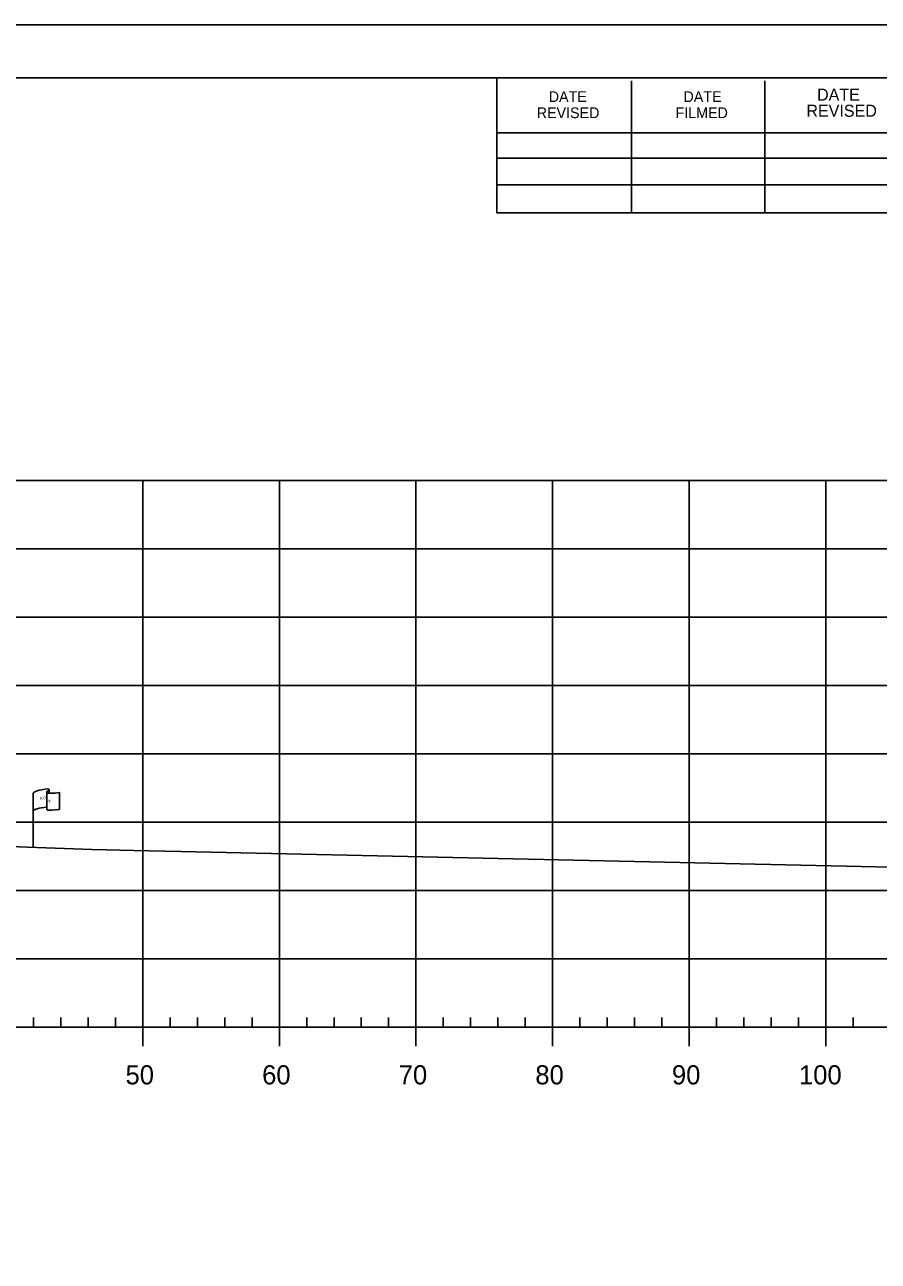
# Model space of a CAD drawing. Extents: x 1370843 to 1371177, y 380307 to 382654.
# Drawn here: x 1371055.1 to 1371117.6, y 380857 to 380947.5 of the extents above; entities that cross this region are included whole.
import ezdxf

# ---------------------------------------------------------------- set-up
doc = ezdxf.new("R2010")
doc.units = 0
for name, color, linetype in [('R_Axis', 7, 'Continuous'), ('R_Axis Annot', 7, 'Continuous'), ('R_Border', 7, 'Continuous'), ('R_Exist Surface', 7, 'Continuous'), ('R_Grid', 7, 'Continuous'), ('R_No Plot', 7, 'Continuous'), ('R_ROW', 7, 'Continuous')]:
    doc.layers.add(name, color=color, linetype=linetype)

msp = doc.modelspace()

# ---------------------------------------------------------------- linework, layer by layer
at = {"layer": 'R_Axis'}
for p, q in [((1371055.709, 380874.124), (1371055.709, 380874.824)), ((1371057.709, 380874.124), (1371057.709, 380874.824)), ((1371059.709, 380874.124), (1371059.709, 380874.824)), ((1371061.709, 380874.124), (1371061.709, 380874.824)), ((1371065.709, 380874.124), (1371065.709, 380874.824)), ((1371067.709, 380874.124), (1371067.709, 380874.824)), ((1371069.709, 380874.124), (1371069.709, 380874.824)), ((1371071.709, 380874.124), (1371071.709, 380874.824)), ((1371075.709, 380874.124), (1371075.709, 380874.824)), ((1371077.709, 380874.124), (1371077.709, 380874.824)), ((1371079.709, 380874.124), (1371079.709, 380874.824)), ((1371081.709, 380874.124), (1371081.709, 380874.824)), ((1371085.709, 380874.124), (1371085.709, 380874.824)), ((1371087.709, 380874.124), (1371087.709, 380874.824)), ((1371089.709, 380874.124), (1371089.709, 380874.824)), ((1371091.709, 380874.124), (1371091.709, 380874.824)), ((1371095.709, 380874.124), (1371095.709, 380874.824)), ((1371097.709, 380874.124), (1371097.709, 380874.824)), ((1371099.709, 380874.124), (1371099.709, 380874.824)), ((1371101.709, 380874.124), (1371101.709, 380874.824)), ((1371105.709, 380874.124), (1371105.709, 380874.824)), ((1371107.709, 380874.124), (1371107.709, 380874.824)), ((1371109.709, 380874.124), (1371109.709, 380874.824)), ((1371111.709, 380874.124), (1371111.709, 380874.824)), ((1371115.709, 380874.124), (1371115.709, 380874.824)), ((1370868.709, 380874.124), (1371158.709, 380874.124)), ((1371063.709, 380872.724), (1371063.709, 380874.124)), ((1371073.709, 380872.724), (1371073.709, 380874.124)), ((1371083.709, 380872.724), (1371083.709, 380874.124)), ((1371093.709, 380872.724), (1371093.709, 380874.124)), ((1371103.709, 380872.724), (1371103.709, 380874.124)), ((1371113.709, 380872.724), (1371113.709, 380874.124))]:
    msp.add_line(p, q, dxfattribs=at)
at = {"layer": 'R_Border'}
for p, q in [((1370855.709, 380943.584), (1371171.889, 380943.584)), ((1371089.629, 380933.704), (1371089.629, 380943.584)), ((1371099.489, 380933.704), (1371099.489, 380943.384)), ((1371109.249, 380933.704), (1371109.249, 380943.384)), ((1371089.629, 380939.564), (1371128.789, 380939.564)), ((1371089.629, 380937.704), (1371128.789, 380937.704)), ((1371089.629, 380933.704), (1371089.629, 380935.764)), ((1371089.629, 380935.764), (1371128.789, 380935.764)), ((1371171.889, 380933.704), (1371089.629, 380933.704))]:
    msp.add_line(p, q, dxfattribs=at)
at = {"layer": 'R_Exist Surface'}
msp.add_line((1371066.491, 380886.977), (1371158.705, 380884.921), dxfattribs=at)
msp.add_lwpolyline([(1370903.417, 380888.697), (1370918.564, 380889.115), (1370955.916, 380890.13), (1370960.694, 380891.163), (1370968.129, 380892.917), (1370971.809, 380893.102), (1370973.674, 380893.219), (1370977.358, 380893.146), (1370983.965, 380893.036), (1370992.11, 380892.507), (1370995.338, 380892.29), (1371003.468, 380890.494), (1371005.95, 380889.961), (1371012.172, 380889.071), (1371013.91, 380888.825), (1371015.648, 380888.774), (1371022.509, 380888.613), (1371055.267, 380887.283), (1371059.995, 380887.112), (1371063.063, 380887.048), (1371064.162, 380887.025), (1371066.491, 380886.977)], dxfattribs=at)
at = {"layer": 'R_Grid'}
for p, q in [((1370868.709, 380914.124), (1371158.709, 380914.124)), ((1371063.709, 380874.124), (1371063.709, 380914.124)), ((1371073.709, 380874.124), (1371073.709, 380914.124)), ((1371083.709, 380874.124), (1371083.709, 380914.124)), ((1371093.709, 380874.124), (1371093.709, 380914.124)), ((1371103.709, 380874.124), (1371103.709, 380914.124)), ((1371113.709, 380874.124), (1371113.709, 380914.124)), ((1370868.709, 380909.124), (1371158.709, 380909.124)), ((1370868.709, 380904.124), (1371158.709, 380904.124)), ((1370868.709, 380899.124), (1371158.709, 380899.124)), ((1370868.709, 380894.124), (1371158.709, 380894.124)), ((1370868.709, 380889.124), (1371158.709, 380889.124)), ((1370868.709, 380884.124), (1371158.709, 380884.124)), ((1370868.709, 380879.124), (1371158.709, 380879.124)), ((1370868.709, 380874.124), (1371158.709, 380874.124))]:
    msp.add_line(p, q, dxfattribs=at)
at = {"layer": 'R_No Plot'}
msp.add_line((1370843.308, 380947.479), (1371176.642, 380947.479), dxfattribs=at)
for points in [[(1370843.302, 380947.479), (1371176.642, 380947.479), (1371176.642, 380734.141), (1370843.302, 380734.141)], [(1371089.629, 380943.584), (1371089.629, 380933.704), (1371125.361, 380933.704), (1371125.361, 380930.784), (1371148.561, 380930.784), (1371148.561, 380906.452), (1371171.889, 380906.452), (1371171.889, 380738.124), (1370855.709, 380738.124), (1370855.709, 380943.584)]]:
    msp.add_lwpolyline(points, close=True, dxfattribs=at)
at = {"layer": 'R_ROW'}
for p, q in [((1371055.684, 380887.268), (1371055.684, 380891.218)), ((1371056.679, 380891.313), (1371056.679, 380891.3)), ((1371056.679, 380891.3), (1371056.679, 380890.073)), ((1371056.847, 380891.469), (1371056.847, 380891.229)), ((1371057.614, 380891.276), (1371057.614, 380890.035))]:
    msp.add_line(p, q, dxfattribs=at)
for centre, radius, start, end in [((1371056.757, 380891.313), 0.078, 88.6458, 274.28284), ((1371056.768, 380891.469), 0.0783, 263.07118, 93.95638), ((1371056.758, 380890.073), 0.0783, 180, 273.95638)]:
    msp.add_arc(centre, radius, start, end, dxfattribs=at)
for centre, major_axis, ratio, start_param, end_param in [((1371057.266, 380891.262), (-1.582, -0.043), 0.19887, 5.030368, 6.283185), ((1371057.973, 380891.377), (-1.227, -0.134), 0.052933, 0.159456, 1.268315), ((1371057.26, 380889.944), (-1.582, -0.043), 0.19887, 5.083035, 6.194897), ((1371057.973, 380890.137), (-1.227, -0.134), 0.052933, 0.159456, 1.268315)]:
    msp.add_ellipse(centre, major_axis=major_axis, ratio=ratio, start_param=start_param, end_param=end_param, dxfattribs=at)

# ---------------------------------------------------------------- texts
at = {"layer": 'R_Axis Annot'}
for s, p in [('50', (1371062.448, 380869.924)), ('60', (1371072.448, 380869.924)), ('70', (1371082.448, 380869.924)), ('80', (1371092.448, 380869.924)), ('90', (1371102.448, 380869.924)), ('100', (1371111.748, 380869.924))]:
    msp.add_text(s, height=1.4, dxfattribs=at).set_placement(p)
at = {"layer": 'R_Border'}
for s, height, p in [('DATE', 0.7819, (1371093.429, 380941.824)), ('DATE', 0.7819, (1371103.289, 380941.824)), ('DATE', 0.8792, (1371113.069, 380941.924)), ('REVISED', 0.8792, (1371112.289, 380940.744)), ('REVISED', 0.7819, (1371092.549, 380940.644)), ('FILMED', 0.7819, (1371102.709, 380940.644))]:
    msp.add_text(s, height=height, rotation=360, dxfattribs=at).set_placement(p)
at = {"layer": 'R_ROW'}
for s, height, rotation, p in [('R ', 0.2, 9.98841, (1371056.203, 380890.72)), (' O', 0.2, 9.98841, (1371056.349, 380890.765)), ('DWB 11-9-07', 0.001, 90, (1371056.846, 380891.229)), ('W', 0.2, 351.17882, (1371056.679, 380890.596)), ('DWB 11-9-07', 0.001, 5.07169, (1371057.604, 380890.035)), ('DWB 11-9-07', 0.001, 90, (1371055.683, 380887.268))]:
    msp.add_text(s, height=height, rotation=rotation, dxfattribs=at).set_placement(p)

doc.saveas('drawing.dxf')
